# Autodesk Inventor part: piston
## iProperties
Created: 2011-09
Part Number: piston
Document SubType Name: Modeling
Designer: Dominique
Author: Dominique
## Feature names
1. Révolution1 [Revolution]
2. Révolution2 [Revolution]
